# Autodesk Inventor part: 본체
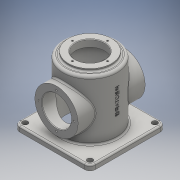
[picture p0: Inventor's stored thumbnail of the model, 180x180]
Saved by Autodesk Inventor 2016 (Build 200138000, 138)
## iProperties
Created: 2019-08
Part Number: 본체
Material: 일반
Document SubType Name: Modeling
Designer: user
Density: 1 g/cm^3
Appearance: 기본값
Author: user
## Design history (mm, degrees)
sketch "스케치1"
  geometry: C1 r 50 at (0, 0); 1 further point
  constraints: 1 centre point, 1 coincident
  dimensions: "d0" = 100 diameter of C1
extrude "돌출1" new body sketch "스케치1" distance "d1" = 120; taper "d2" = 0 deg
sketch "스케치2"
  geometry: C1 r 45 at (0, 0); 1 further point
  constraints: 1 centre point, 1 coincident
  dimensions: "d3" = 90 diameter of C1
extrude "돌출2" cut sketch "스케치2" distance "d4" = 112; taper "d5" = 0 deg
sketch "스케치3"
  geometry: L1 (-60, -70)-(60, -70); L2 (70, -60)-(70, 60); L3 (60, 70)-(-60, 70); L4 (-70, 60)-(-70, -60); L5 (-70, -70)-(70, 70); L6 (70, -70)-(-70, 70); C1 r 50 at (0, 0); A1 r 10 centre (60, 60) between (70, 60) and (60, 70); A2 r 10 centre (-60, 60) between (-60, 70) and (-70, 60); A3 r 10 centre (-60, -60) between (-70, -60) and (-60, -70); A4 r 10 centre (60, -60) between (60, -70) and (70, -60); 1 further point
  constraints: 12 end point, 8 point on circle, 8 point on line, 8 tangent, 5 centre point, 3 equal radius, 2 midpoint, 2 parallel, 2 perpendicular, 1 coincident, 1 horizontal
  dimensions: "d6" = 140 distance of L6.start L5.end; "d7" = 100 diameter of C1; "d10" = 10 radius of A1
extrude "돌출3" join sketch "스케치3" distance "d8" = 10; taper "d9" = 0 deg
sketch "스케치4"
  geometry: C1 r 40 at (0, 0); 1 further point
  constraints: 1 centre point, 1 coincident
  dimensions: "d11" = 80 diameter of C1
extrude "돌출4" join sketch "스케치4" distance "d12" = 5; taper "d13" = 0 deg
hole "구멍1" diameter "d16" = 54; stored, may be unused: countersink angle "d20" = 90 deg, drill point angle "d22" = 118 deg; dims "d14" = 10, "d15" = 10, "d17" = 6, "d18" = 4, "d19" = 2, "d21" = 8
sketch "스케치5"
  geometry: A1 r 32.5 centre (0, 0) between (32.5, 0) and (-32.5, 0); 3 further points
  constraints: 4 point on circle, 1 centre point, 1 coincident
  dimensions: "d23" = 65 diameter of A1
hole "구멍2" sketch "스케치5" at (32.5, 0), (-32.5, 0), (0, 32.5), (0, -32.5) diameter "d24" = 3.242; stored, may be unused: countersink angle "d28" = 90 deg, drill point angle "d30" = 118 deg; dims "d25" = 8, "d26" = 4, "d27" = 2, "d29" = 10
node "작업 평면1"
sketch "스케치6"
  geometry: L1 (60, 0)-(-60, 0) reference; C1 r 40 at (0, 60); 2 further points
  constraints: 1 centre point, 1 midpoint, 1 vertical alignment
  dimensions: "d32" = 80 diameter of C1; "d33" = 60 distance from line of L1 C1.centre
extrude "돌출5" join sketch "스케치6" stored distance "d34" = 10; taper "d35" = 0 deg
sketch "스케치7"
  geometry: 1 further point
hole "구멍3" diameter "d38" = 54; stored, may be unused: countersink angle "d42" = 90 deg, drill point angle "d44" = 118 deg; dims "d36" = 10, "d37" = 10, "d39" = 6, "d40" = 4, "d41" = 2, "d43" = 8
sketch "스케치8"
  geometry: A1 r 32.5 centre (0, 0) between (0, 32.5) and (-32.5, 0); 3 further points
  constraints: 4 point on circle, 1 centre point
  dimensions: "d45" = 65 diameter of A1
hole "구멍4" sketch "스케치8" at (32.5, 0), (0, 32.5), (-32.5, 0), (0, -32.5) diameter "d46" = 3.242; stored, may be unused: countersink angle "d50" = 90 deg, drill point angle "d52" = 118 deg; dims "d47" = 8, "d48" = 4, "d49" = 2, "d51" = 10
sketch "스케치9"
  geometry: A1 r 10 centre (-60, -60) between (-70, -60) and (-60, -70) reference; A2 r 10 centre (60, -60) between (60, -70) and (70, -60) reference; A3 r 10 centre (-60, 60) between (-60, 70) and (-70, 60) reference; A4 r 10 centre (60, 60) between (70, 60) and (60, 70) reference; 5 further points
  constraints: 4 coincident
hole "구멍5" sketch "스케치9" at (60, -60), (60, 60), (-60, -60), (-60, 60) diameter "d53" = 10; stored, may be unused: countersink angle "d57" = 90 deg, drill point angle "d59" = 118 deg; dims "d54" = 8, "d55" = 4, "d56" = 2, "d58" = 10
node "작업 평면2"
sketch "스케치10"
  geometry: L1 (-60, 0)-(60, 0) reference; 4 further points
  constraints: 2 midpoint, 1 vertical alignment, 1 other
  dimensions: "d65" = 70 distance of point (0, 0) point (0, 70)
feature "엠보싱1" sketch "스케치10" dims "d61" = 0.5, "d62" = 0
fillet "모깎기1" dims "d63" = 5, "d64" = 3
chamfer "모따기1" distance "d66" = 1; stored, may be unused: second distance "d67" = 2, angle "d68" = 45 deg
node "솔리드1"
mirror "대칭1"
other parameters: "d31" = -62
